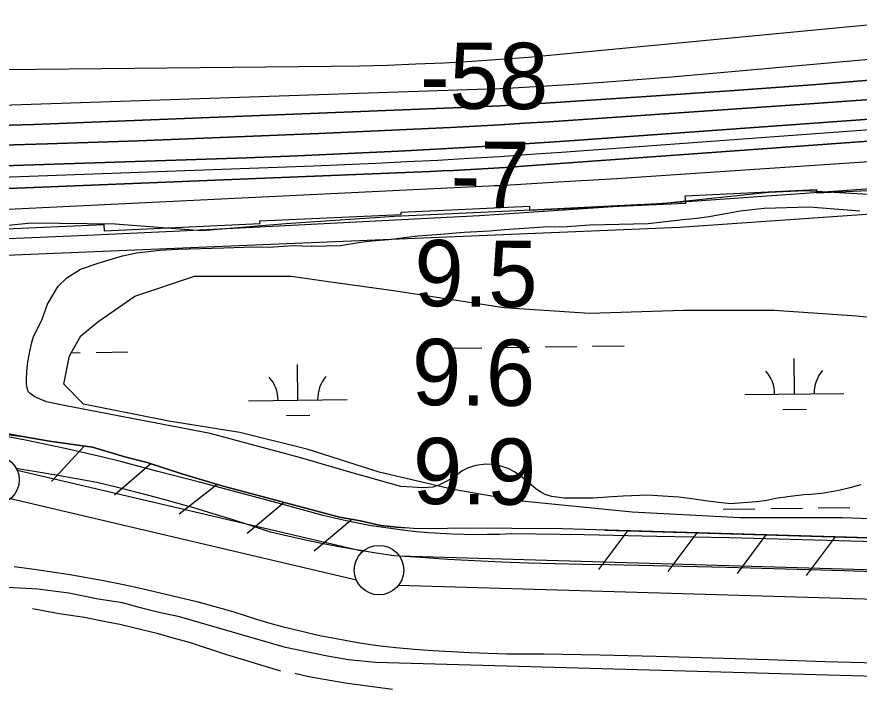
# Model space of a CAD drawing. Extents: x 3704301 to 3742427, y 506229 to 532009.
# Drawn here: x 3717817 to 3718668, y 518487 to 519168 of the extents above; entities that cross this region are included whole.
import ezdxf

# ---------------------------------------------------------------- set-up
doc = ezdxf.new("R2010")
doc.units = 0
for name, color, linetype in [('V-FLOD-BASE', 7, 'Continuous'), ('V-LEVE-TOET', 7, 'Continuous'), ('V-RIVR-EDGE', 7, 'Continuous'), ('V-RIVR-RANG', 7, 'Continuous'), ('V-ROAD-CNTR', 7, 'Continuous'), ('V-RRAP-FSHR', 7, 'Continuous'), ('V-RRAP-RVMT', 7, 'Continuous'), ('V-SITE-VEGE', 7, 'Continuous'), ('V-SURV-LINE', 7, 'Continuous'), ('V-TOPO-DPTH', 7, 'Continuous'), ('V-TOPO-MAJR', 7, 'Continuous'), ('V-TOPO-MINR', 7, 'Continuous'), ('V-TOPO-SHOR', 7, 'Continuous'), ('V-TOPO-WATR', 7, 'Continuous'), ('V-WETL-SWMP', 7, 'Continuous')]:
    doc.layers.add(name, color=color, linetype=linetype)

msp = doc.modelspace()

# ---------------------------------------------------------------- linework, layer by layer
at = {"layer": 'V-FLOD-BASE'}
msp.add_lwpolyline([(3718712.041, 518605.60000000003), (3718652.663, 518607.613), (3718593.279, 518609.423), (3718533.887, 518611.03500000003), (3718474.4930000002, 518612.446), (3718415.093, 518613.657), (3718387.9020000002, 518614.04600000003), (3718360.713, 518614.656), (3718333.5300000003, 518615.481), (3718306.353, 518616.528), (3718279.186, 518617.791), (3718252.031, 518619.272), (3718224.887, 518620.972), (3718197.759, 518622.891), (3718179.798, 518625.588), (3718161.8740000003, 518628.521), (3718143.989, 518631.681), (3718126.147, 518635.077), (3718108.352, 518638.699), (3718090.6040000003, 518642.556), (3718072.9050000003, 518646.64), (3718053.67, 518653.132), (3718034.36, 518659.397), (3718014.977, 518665.434), (3717995.524, 518671.242), (3717976.002, 518676.821), (3717956.419, 518682.168), (3717936.773, 518687.286), (3717917.0670000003, 518692.17100000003), (3717897.306, 518696.824), (3717876.924, 518700.766), (3717856.495, 518704.45300000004), (3717836.023, 518707.885), (3717815.508, 518711.059)], dxfattribs=at)
at = {"layer": 'V-LEVE-TOET'}
for points in [[(3718220.578, 518647.197), (3718208.657, 518648.468), (3718196.7600000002, 518649.963), (3718184.892, 518651.68), (3718173.058, 518653.615), (3718161.262, 518655.77400000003), (3718149.509, 518658.14900000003), (3718137.802, 518660.746), (3718126.147, 518663.56), (3718084.523, 518675.043), (3718042.826, 518686.264), (3718001.063, 518697.22500000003), (3717959.231, 518707.924), (3717940.254, 518713.126), (3717921.218, 518718.11100000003), (3717902.129, 518722.878), (3717882.984, 518727.427), (3717863.788, 518731.757), (3717844.545, 518735.865), (3717825.257, 518739.75200000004), (3717805.924, 518743.42)], [(3718683.991, 518636.879), (3718610.483, 518638.994), (3718536.97, 518640.868), (3718463.449, 518642.507), (3718389.923, 518643.903), (3718316.396, 518645.061), (3718304.415, 518644.544), (3718292.4280000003, 518644.254), (3718280.437, 518644.184), (3718268.446, 518644.34), (3718256.463, 518644.719), (3718244.487, 518645.32300000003), (3718232.524, 518646.148), (3718220.578, 518647.197)], [(3717813.931, 518611.887), (3717831.88, 518609.61600000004), (3717849.802, 518607.14400000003), (3717868.535, 518604.12700000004), (3717887.227, 518600.87700000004), (3717905.878, 518597.393), (3717924.485, 518593.67600000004), (3717943.044, 518589.728), (3717961.551, 518585.548)], [(3717961.551, 518585.548), (3717980.006, 518581.136), (3717998.403, 518576.494), (3718016.741, 518571.621), (3718035.015, 518566.52), (3718047.362, 518562.43), (3718059.7770000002, 518558.55100000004), (3718072.258, 518554.887), (3718084.798, 518551.434), (3718097.395, 518548.19800000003), (3718110.048, 518545.178), (3718122.747, 518542.37200000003), (3718135.494, 518539.78500000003), (3718148.284, 518537.416), (3718161.113, 518535.265), (3718173.9760000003, 518533.33400000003), (3718186.8680000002, 518531.624), (3718199.789, 518530.13300000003), (3718218.424, 518528.54000000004), (3718237.073, 518527.17), (3718255.738, 518526.021), (3718274.416, 518525.097), (3718293.1040000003, 518524.39400000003), (3718311.798, 518523.91500000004), (3718330.4960000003, 518523.661), (3718349.199, 518523.629), (3718405.984, 518522.57800000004), (3718462.764, 518521.275), (3718519.537, 518519.719), (3718576.306, 518517.91000000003), (3718633.0640000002, 518515.85000000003), (3718725.975, 518513.597)]]:
    msp.add_lwpolyline(points, dxfattribs=at)
at = {"layer": 'V-RIVR-EDGE'}
msp.add_lwpolyline([(3716966.3291806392, 518953.0583641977), (3717011.9641167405, 518957.1478085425), (3717095.394164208, 518950.9382436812), (3717250.2656130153, 518945.7526780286), (3717348.706703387, 518940.706648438), (3717388.3072369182, 518932.2041548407), (3717429.7146770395, 518926.0984998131), (3717467.5647121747, 518938.0114402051), (3717522.7988779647, 518939.6758418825), (3717620.0452601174, 518937.0340729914), (3717683.0954998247, 518943.4817608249), (3717736.540572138, 518949.9531994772), (3717831.4153509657, 518959.3238275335), (3717916.059404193, 518958.514200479), (3718003.690227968, 518951.6939216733), (3718088.3535787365, 518958.6884931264), (3718198.2319783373, 518966.2210416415), (3718336.3225883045, 518972.4831762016), (3718470.8127449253, 518979.35454028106), (3718576.497790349, 518990.499417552), (3718613.121944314, 518992.20983644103), (3718677.3475947, 518988.4490650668)], dxfattribs=at)
at = {"layer": 'V-ROAD-CNTR'}
msp.add_lwpolyline([(3718780.984399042, 518498.22397736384), (3718179.10160281, 518515.0229437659), (3718151.7466575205, 518517.6219385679), (3718130.4017002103, 518521.2299313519), (3718088.0457849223, 518529.98591383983), (3717980.9049992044, 518561.00785179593), (3717958.8460433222, 518565.946841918), (3717941.690077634, 518570.39283302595), (3717923.510113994, 518575.14582351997), (3717898.816163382, 518579.17281546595), (3717869.023222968, 518584.9978038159), (3717837.850285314, 518589.07379566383), (3717807.083346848, 518590.79779221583), (3717763.1384347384, 518593.4077869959), (3717074.307812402, 518630.34071313), (3717017.92392517, 518633.024707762), (3716960.9360391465, 518633.922705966), (3716927.571105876, 518635.51070279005), (3716890.6951796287, 518634.1547055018), (3716848.315264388, 518631.50571079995), (3716792.891375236, 518627.14471952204), (3716349.319262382, 518566.5998406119)], dxfattribs=at)
at = {"layer": 'V-RRAP-FSHR'}
for p, q in [((3717884.681, 518733.82300000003), (3717851.525, 518697.97500000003)), ((3717952.3030000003, 518716.052), (3717915.291, 518684.2)), ((3718019.06, 518694.981), (3717980.66, 518664.816)), ((3718086.668, 518676.846), (3718049.3140000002, 518645.395)), ((3718154.313, 518658.843), (3718116.96, 518627.392)), ((3718433.687, 518648.256), (3718404.524, 518609.09)), ((3718503.657, 518646.21400000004), (3718474.494, 518607.048)), ((3718573.627, 518644.172), (3718544.464, 518605.006)), ((3718643.597, 518642.131), (3718614.435, 518602.965))]:
    msp.add_line(p, q, dxfattribs=at)
for points in [[(3713987.6284698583, 518174.2519979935), (3714448.770486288, 518564.7359663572), (3714742.224310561, 518696.92822248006), (3715881.889207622, 518753.2748465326), (3716266.2537519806, 518793.8989745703), (3716843.0852405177, 518890.7407026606), (3717110.3349047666, 518911.17564667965), (3717741.270457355, 518924.00227069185), (3718486.4311620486, 518954.9455027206), (3719294.778810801, 519011.24502277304), (3719786.2598992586, 519085.7553588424), (3720431.328699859, 519110.59350286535), (3720895.931836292, 519113.0777268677), (3721218.4652125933, 519068.37193482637), (3721397.6508767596, 519012.4881587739), (3721721.322941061, 518965.4353587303), (3721950.5678692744, 518904.45001467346), (3722606.869949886, 518712.51759849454), (3722865.6920941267, 518669.46659045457), (3723100.4830063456, 518674.84873445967), (3723533.3831027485, 518647.1433904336), (3724154.011071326, 518572.98531036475), (3724673.74841581, 518469.1639982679)], [(3718861.522, 518635.772), (3718367.7, 518650.181), (3718265.843, 518650.62200000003), (3718237.823, 518650.141), (3718217.366, 518650.597), (3718200.308, 518651.668), (3718184.58, 518653.45300000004), (3718163.802, 518658.071), (3718142.728, 518661.92600000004), (3718022.926, 518693.81), (3717983.316, 518705.806), (3717948.3370000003, 518717.06200000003), (3717925.798, 518722.80100000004), (3717893.086, 518732.653), (3717875.83, 518735.03), (3717849.559, 518738.613), (3717822.3030000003, 518743.281), (3717746.779, 518757.76300000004)], [(3717742.5870000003, 518753.401), (3717822.3030000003, 518743.281), (3717849.559, 518738.613), (3717875.83, 518735.03), (3717893.086, 518732.653), (3717925.798, 518722.80100000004), (3717948.3370000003, 518717.06200000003), (3717983.316, 518705.806), (3718022.926, 518693.81), (3718142.728, 518661.92600000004), (3718163.802, 518658.071), (3718184.58, 518653.45300000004), (3718200.308, 518651.668), (3718210.741, 518651.01300000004)], [(3718410.894, 518648.92100000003), (3718861.522, 518635.772)]]:
    msp.add_lwpolyline(points, dxfattribs=at)
at = {"layer": 'V-RRAP-RVMT'}
for points in [[(3718492.1660000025, 518986.82400000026), (3718624.7510000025, 518993.0070000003), (3718624.9080000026, 518989.72200000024), (3718765.6540000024, 518996.2240000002)], [(3717782.7630000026, 518952.31400000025), (3717904.6080000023, 518957.8810000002), (3717904.9230000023, 518951.37500000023), (3718062.4720000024, 518958.60700000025), (3718062.2990000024, 518961.30800000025), (3718205.1560000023, 518967.8820000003), (3718204.9980000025, 518970.3600000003), (3718334.5870000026, 518976.3660000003), (3718334.7830000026, 518972.13400000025), (3718492.5710000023, 518979.4360000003), (3718492.1660000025, 518986.82400000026)]]:
    msp.add_lwpolyline(points, dxfattribs=at)
at = {"layer": 'V-SITE-VEGE'}
for points in [[(3718304.804, 518713.837), (3718297.348, 518715.102), (3718290.18, 518715.618), (3718280.603, 518714.215), (3718272.81, 518711.89900000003), (3718266.808, 518708.819), (3718262.894, 518705.718), (3718256.273, 518700.85000000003), (3718246.965, 518696.158), (3718243.215, 518694.401), (3718236.919, 518692.369), (3718227.199, 518691.565), (3718204.651, 518692.824), (3718155.329, 518706.738), (3718102.288, 518722.332), (3718012.123, 518746.496), (3717917.122, 518764.727), (3717864.4760000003, 518774.789), (3717846.433, 518778.545), (3717835.421, 518783.282), (3717832.599, 518784.95300000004), (3717829.926, 518786.772), (3717828.1550000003, 518789.02900000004), (3717827.1410000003, 518792.326), (3717826.432, 518796.367), (3717826.48, 518801.446), (3717826.699, 518808.765), (3717827.5160000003, 518816.079), (3717828.6380000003, 518824.28500000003), (3717831.452, 518837.407), (3717833.3140000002, 518844.56), (3717841.8370000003, 518861.063), (3717847.519, 518877.146), (3717858.447, 518895.271), (3717867.042, 518903.705), (3717880.8740000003, 518912.68700000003), (3717899.909, 518918.929), (3717923.436, 518926.179), (3717937.508, 518929.184), (3717961.287, 518931.797), (3717978.927, 518932.67600000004), (3718025.8540000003, 518934.023), (3718046.181, 518934.728), (3718059.032, 518935.053), (3718071.58, 518934.78500000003), (3718095.204, 518936.503), (3718114.6210000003, 518935.868), (3718143.764, 518936.64), (3718163.8140000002, 518939.737), (3718175.481, 518941.271), (3718192.5270000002, 518942.602), (3718222, 518946.356), (3718240.685, 518947.673), (3718268.796, 518949.946), (3718294.21, 518951.499), (3718309.609, 518952.697), (3718348.781, 518955.46400000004), (3718372.54, 518955.68700000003), (3718395.717, 518957.559), (3718454.595, 518958.794), (3718489.747, 518962.943), (3718503.8000000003, 518964.153), (3718516.219, 518965.829), (3718547.65, 518971.653), (3718572.029, 518974.262), (3718617.46, 518975.477), (3718668.6720000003, 518971.702)], [(3718669.481, 518694.69), (3718658.545, 518691.657), (3718647.3140000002, 518688.927), (3718632.495, 518686.07800000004), (3718619.3340000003, 518684.708), (3718612.0100000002, 518684.329), (3718598.25, 518682.815), (3718583.588, 518680.864), (3718574.454, 518678.707), (3718563.983, 518677.315), (3718537.369, 518675.326), (3718514.536, 518678.08), (3718500.96, 518680.153), (3718485.589, 518682.242), (3718469.613, 518683.291), (3718454.23, 518684.032), (3718429.271, 518683.223), (3718418.208, 518682.582), (3718398.92, 518680.97000000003), (3718369.6380000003, 518681.099), (3718357.401, 518682.70900000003), (3718351.292, 518684.411), (3718346.682, 518686.696), (3718341.486, 518690.18200000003), (3718336.298, 518694.712), (3718325.921, 518703.33), (3718319.687, 518707.719), (3718312.9960000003, 518711.07), (3718304.804, 518713.837)]]:
    msp.add_lwpolyline(points, dxfattribs=at)
at = {"layer": 'V-SURV-LINE'}
for points in [[(3717816.8832654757, 518709.58123429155), (3718166.5543926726, 518627.5493246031)], [(3718159.721601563, 518598.33779690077), (3717810.0503576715, 518680.3697339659)], [(3718203.024592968, 518622.78693472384), (3719352.0420055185, 518589.125581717)], [(3719351.1427772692, 518559.13905443), (3718202.1245078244, 518592.80043253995)]]:
    msp.add_lwpolyline(points, dxfattribs=at)
for centre in [(3717794.00973, 518699.54000000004), (3718182.5951, 518608.3791199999)]:
    msp.add_circle(centre, 25, dxfattribs=at)
at = {"layer": 'V-TOPO-DPTH'}
for points in [[(3718699.3019376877, 519105.46070434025), (3718620.486111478, 519099.0668083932), (3718541.6253002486, 519093.25399335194), (3718462.734499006, 519087.82856558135), (3718335.335299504, 519079.5387600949), (3718320.1185920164, 519078.6061987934), (3718304.897870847, 519077.7501430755), (3718289.671129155, 519077.0088457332), (3718274.44037378, 519076.34405397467), (3717892.8630240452, 519061.12969407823), (3717833.7136135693, 519058.9515397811), (3717774.557069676, 519057.01343739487)], [(3718699.3019376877, 519105.46070434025), (3718620.486111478, 519099.0668083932), (3718541.6253002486, 519093.25399335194), (3718462.734499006, 519087.82856558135), (3718335.335299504, 519079.5387600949), (3718320.1185920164, 519078.6061987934), (3718304.897870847, 519077.7501430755), (3718289.671129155, 519077.0088457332), (3718274.44037378, 519076.34405397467), (3717892.8630240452, 519061.12969407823), (3717833.7136135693, 519058.9515397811), (3717774.557069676, 519057.01343739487)], [(3718712.2537406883, 519086.4777821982), (3718622.3327865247, 519080.0281007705), (3718354.4747839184, 519061.65410850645), (3718329.625712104, 519060.0335402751), (3718304.7702459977, 519058.5244938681), (3718279.905188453, 519057.1827301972), (3718255.033736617, 519055.9524883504), (3718121.96722468, 519049.8192097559), (3718030.5477249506, 519045.88412920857), (3717939.114898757, 519042.31988417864), (3717847.6620828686, 519039.3118924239), (3717756.195940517, 519036.6747361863)], [(3717756.195940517, 519036.6747361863), (3717847.6620828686, 519039.3118924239), (3717939.114898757, 519042.31988417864), (3718030.5477249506, 519045.88412920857), (3718121.96722468, 519049.8192097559), (3718255.033736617, 519055.9524883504), (3718279.905188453, 519057.1827301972), (3718304.7702459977, 519058.5244938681), (3718329.625712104, 519060.0335402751), (3718354.4747839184, 519061.65410850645), (3718622.3327865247, 519080.0281007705), (3718712.2537406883, 519086.4777821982)], [(3718902.495740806, 519080.27577819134), (3718375.1559906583, 519042.42865107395), (3718339.898950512, 519040.00197755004), (3718304.633379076, 519037.7129755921), (3718269.355010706, 519035.6304809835), (3718234.068111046, 519033.6856579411), (3718202.403106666, 519032.0334167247), (3718151.2709634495, 519029.51527815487), (3718100.1303643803, 519027.1965147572), (3718048.9770815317, 519025.1768141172), (3717997.815342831, 519023.35648864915), (3717607.713847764, 519010.61857388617)], [(3717607.713847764, 519010.61857388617), (3717997.815342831, 519023.35648864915), (3718048.9770815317, 519025.1768141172), (3718100.1303643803, 519027.1965147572), (3718151.2709634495, 519029.51527815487), (3718202.403106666, 519032.0334167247), (3718234.068111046, 519033.6856579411), (3718269.355010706, 519035.6304809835), (3718304.633379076, 519037.7129755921), (3718339.898950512, 519040.00197755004), (3718375.1559906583, 519042.42865107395), (3718902.495740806, 519080.27577819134)], [(3717557.4663779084, 518984.1171311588), (3718234.433780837, 519011.368021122), (3718246.11894899, 519011.8690423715), (3718257.8021193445, 519012.4108369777), (3718269.482293, 519013.0137916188), (3718281.160468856, 519013.6575196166), (3718292.8354627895, 519014.35766745), (3718304.508212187, 519015.0922642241), (3718316.17759478, 519015.8785344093), (3718327.8447328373, 519016.6992535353), (3718705.354464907, 519044.09497185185)], [(3718705.354464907, 519044.09497185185), (3718327.8447328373, 519016.6992535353), (3718316.17759478, 519015.8785344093), (3718304.508212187, 519015.0922642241), (3718292.8354627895, 519014.35766745), (3718281.160468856, 519013.6575196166), (3718269.482293, 519013.0137916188), (3718257.8021193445, 519012.4108369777), (3718246.11894899, 519011.8690423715), (3718234.433780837, 519011.368021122), (3717557.4663779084, 518984.1171311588)], [(3717800.1142852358, 518943.1619353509), (3717887.325687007, 518946.8199402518), (3717974.518386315, 518950.8994973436), (3718061.698617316, 518955.2600892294), (3718264.199908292, 518965.8795786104), (3718284.2057422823, 518966.9780835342), (3718304.2075957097, 518968.1421989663), (3718324.2034782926, 518969.4047301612), (3718344.195380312, 518970.7328718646), (3718503.795022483, 518981.7302134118), (3718603.578370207, 518988.68168274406), (3718703.354531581, 518995.7337464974)]]:
    msp.add_lwpolyline(points, dxfattribs=at)
at = {"layer": 'V-TOPO-MAJR'}
msp.add_lwpolyline([(3717640.443242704, 519072.9254630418), (3718292.1840048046, 519094.7776057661), (3718298.600294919, 519095.01929502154), (3718305.0149119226, 519095.29633349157), (3718311.4270192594, 519095.62639578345), (3718317.837453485, 519095.9918072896), (3718374.301357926, 519099.4446305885), (3718408.931224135, 519101.7120307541), (3718443.5460726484, 519104.17814465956), (3718478.1383946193, 519106.9423291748), (3718512.715698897, 519109.9052274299), (3719148.4994239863, 519167.1444437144)], dxfattribs=at)
at = {"layer": 'V-TOPO-MINR'}
for points in [[(3717604.023112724, 519112.2690005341), (3718134.3061333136, 519117.82285189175), (3718162.8062598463, 519118.2904253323), (3718191.299570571, 519118.9832953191), (3718219.782657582, 519120.0141101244), (3718248.2589287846, 519121.27022147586), (3718276.715978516, 519122.88903412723), (3718305.154225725, 519124.7659676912), (3718333.5642691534, 519127.03008262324), (3718361.9555100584, 519129.55231846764), (3718866.553351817, 519177.84620950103)], [(3717774.557069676, 519057.01343739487), (3717833.7136135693, 519058.9515397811), (3717892.8630240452, 519061.12969407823), (3718274.44037378, 519076.34405397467), (3718289.671129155, 519077.0088457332), (3718304.897870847, 519077.7501430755), (3718320.1185920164, 519078.6061987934), (3718335.335299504, 519079.5387600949), (3718462.734499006, 519087.82856558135), (3718541.6253002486, 519093.25399335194), (3718620.486111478, 519099.0668083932), (3718699.3019376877, 519105.46070434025)], [(3717756.195940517, 519036.6747361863), (3717847.6620828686, 519039.3118924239), (3717939.114898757, 519042.31988417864), (3718030.5477249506, 519045.88412920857), (3718121.96722468, 519049.8192097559), (3718255.033736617, 519055.9524883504), (3718279.905188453, 519057.1827301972), (3718304.7702459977, 519058.5244938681), (3718329.625712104, 519060.0335402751), (3718354.4747839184, 519061.65410850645), (3718622.3327865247, 519080.0281007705), (3718712.2537406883, 519086.4777821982)], [(3715824.5010770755, 518856.7324853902), (3716585.13, 518985.07), (3717335.5697787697, 518992.56785741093), (3717369.3318325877, 518992.96376627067), (3717403.0926544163, 518993.43777073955), (3717436.851628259, 518994.02891862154), (3717470.6093701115, 518994.6981621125), (3717504.3640205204, 518995.5008274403), (3717538.1157811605, 518996.40328622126), (3717571.8632071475, 518997.45543518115), (3717605.607743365, 518998.6073775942), (3718116.706590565, 519017.1896953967), (3718148.03361091, 519018.41690218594), (3718179.3552586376, 519019.7615478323), (3718210.6688474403, 519021.2823517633), (3718241.9770636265, 519022.9205945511), (3718273.2758258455, 519024.73143512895), (3718304.5673562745, 519026.6549510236), (3718335.848039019, 519028.7474798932), (3718367.1214899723, 519030.95268407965), (3719045.5919869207, 519080.63618425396)], [(3717607.713847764, 519010.61857388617), (3717997.815342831, 519023.35648864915), (3718048.9770815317, 519025.1768141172), (3718100.1303643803, 519027.1965147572), (3718151.2709634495, 519029.51527815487), (3718202.403106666, 519032.0334167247), (3718234.068111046, 519033.6856579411), (3718269.355010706, 519035.6304809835), (3718304.633379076, 519037.7129755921), (3718339.898950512, 519040.00197755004), (3718375.1559906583, 519042.42865107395), (3718902.495740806, 519080.27577819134)], [(3717731.4041646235, 518969.3861207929), (3718293.6427063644, 518996.75430525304), (3718299.0219583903, 518997.0247501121), (3718304.400592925, 518997.30662872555), (3718309.778301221, 518997.6056579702), (3718315.1553920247, 518997.9161209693), (3718363.702224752, 519000.7967945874), (3718393.3501447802, 519002.58981213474), (3718422.9952328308, 519004.4276854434), (3718452.6360729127, 519006.3328423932), (3718482.274081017, 519008.28285510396), (3719134.533887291, 519051.94135970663)], [(3717557.4663779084, 518984.1171311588), (3718234.433780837, 519011.368021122), (3718246.11894899, 519011.8690423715), (3718257.8021193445, 519012.4108369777), (3718269.482293, 519013.0137916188), (3718281.160468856, 519013.6575196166), (3718292.8354627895, 519014.35766745), (3718304.508212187, 519015.0922642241), (3718316.17759478, 519015.8785344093), (3718327.8447328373, 519016.6992535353), (3718705.354464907, 519044.09497185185)]]:
    msp.add_lwpolyline(points, dxfattribs=at)
at = {"layer": 'V-TOPO-SHOR'}
for points in [[(3718083.352, 518506.32300000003), (3718028.789, 518522.58), (3717991.1040000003, 518535.036), (3717972.1780000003, 518540.094), (3717959.636, 518543.92600000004), (3717944.205, 518547.57800000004), (3717920.546, 518553.37), (3717901.062, 518557.197), (3717885.145, 518560.511), (3717859.473, 518564.191), (3717832.3000000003, 518569.19200000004)], [(3718196.1780000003, 518487.655), (3718148.466, 518493.951), (3718111.823, 518500.621), (3718097.555, 518503.712)]]:
    msp.add_lwpolyline(points, dxfattribs=at)
at = {"layer": 'V-TOPO-WATR'}
msp.add_lwpolyline([(3717800.1142852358, 518943.1619353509), (3717887.325687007, 518946.8199402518), (3717974.518386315, 518950.8994973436), (3718061.698617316, 518955.2600892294), (3718264.199908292, 518965.8795786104), (3718284.2057422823, 518966.9780835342), (3718304.2075957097, 518968.1421989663), (3718324.2034782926, 518969.4047301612), (3718344.195380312, 518970.7328718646), (3718503.795022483, 518981.7302134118), (3718603.578370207, 518988.68168274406), (3718703.354531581, 518995.7337464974)], dxfattribs=at)
at = {"layer": 'V-WETL-SWMP'}
for p, q in [((3718254.5560800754, 518832.8587566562), (3718286.5536917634, 518833.249712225)), ((3718302.552497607, 518833.44519000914), (3718334.550109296, 518833.8361455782)), ((3718350.54891514, 518834.03162336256), (3718382.546526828, 518834.4225789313)), ((3718398.545332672, 518834.61805671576), (3718430.54294436, 518835.0090122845)), ((3717871.4833187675, 518828.1782689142), (3717880.6759866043, 518828.29058744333)), ((3717896.674792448, 518828.4860652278), (3717928.6724041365, 518828.8770207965)), ((3718602.4660915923, 518786.3638289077), (3718602.026266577, 518822.3611420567)), ((3718100.595551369, 518780.23183741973), (3718100.1557263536, 518816.2291505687)), ((3718050.599283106, 518779.6209693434), (3718150.591819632, 518780.84270549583)), ((3718552.4698233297, 518785.7529608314), (3718652.4623598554, 518786.9746969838)), ((3718590.6555133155, 518770.7873722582), (3718614.653722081, 518771.0805889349)), ((3718088.784973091, 518764.6553807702), (3718112.7831818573, 518764.94859744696)), ((3718530.4738448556, 518670.04359207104), (3718562.4714565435, 518670.43454763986)), ((3718578.4702623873, 518670.63002542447), (3718610.4678740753, 518671.02098099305)), ((3718626.4666799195, 518671.21645877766), (3718658.464291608, 518671.60741434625))]:
    msp.add_line(p, q, dxfattribs=at)
msp.add_lwpolyline([(3718880.889, 518652.684), (3718651.072, 518661.303), (3718547.654, 518661.303), (3718438.491, 518667.048), (3718323.583, 518678.539), (3718257.5100000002, 518690.03), (3718182.8200000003, 518707.266), (3718111.002, 518730.248), (3718042.057, 518747.484), (3717970.239, 518758.97500000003), (3717884.058, 518776.211), (3717863.949, 518796.32), (3717869.694, 518825.047), (3717881.185, 518845.156), (3717898.421, 518859.52), (3717935.7660000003, 518885.374), (3717996.093, 518905.483), (3718093.7660000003, 518905.483), (3718133.984, 518899.738), (3718197.183, 518891.12), (3718309.219, 518873.88300000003), (3718395.4, 518868.13800000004), (3718490.2, 518871.011), (3718582.127, 518871.011), (3718665.435, 518865.265), (3718748.744, 518856.647)], dxfattribs=at)
for centre, radius, start, end in [((3718547.22147769, 518786.1636737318), 35.24628790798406, 359.9282006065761, 41.47185893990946), ((3718657.6991038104, 518787.5135195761), 35.246287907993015, 139.92819760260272, 181.47185593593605), ((3718045.3509374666, 518780.03168224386), 35.24628790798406, 359.9282006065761, 41.47185893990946), ((3718155.8285635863, 518781.3815280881), 35.246287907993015, 139.92819760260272, 181.47185593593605)]:
    msp.add_arc(centre, radius, start, end, dxfattribs=at)

# ---------------------------------------------------------------- texts
at = {"layer": 'V-RIVR-RANG'}
for s, height, rotation, p in [('-58', 67.00000000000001, 359.7798055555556, (3718223.993538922, 519074.8594635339)), ('-7', 66.99999999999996, 359.49832571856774, (3718254.8528013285, 518974.98317731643)), ('9.5', 66.99999999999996, 359.49832571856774, (3718218.0843913, 518875.301591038)), ('9.6', 66.99999999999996, 359.49832571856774, (3718215.6070053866, 518775.3197581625)), ('9.9', 66.99999999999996, 359.49832571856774, (3718216.5576218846, 518675.30790062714))]:
    msp.add_text(s, height=height, rotation=rotation, dxfattribs=at).set_placement(p)

doc.saveas('drawing.dxf')
